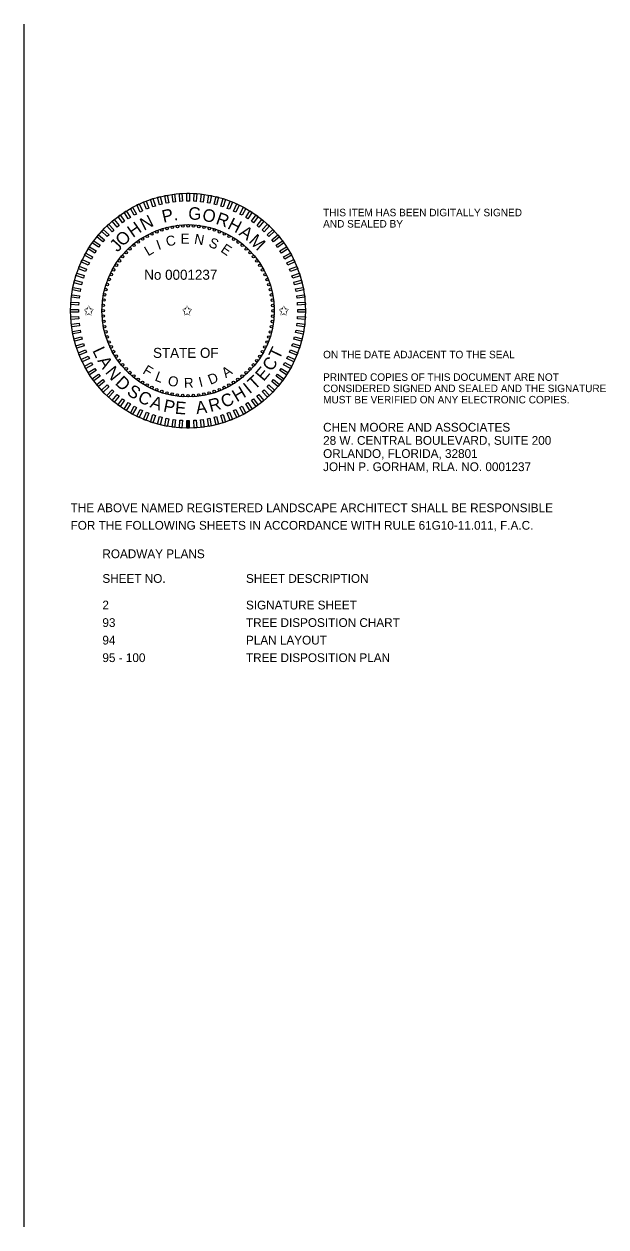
# Model space of a CAD drawing. Extents: x -811 to -790, y -2284 to -2178.
# Drawn here: x -803.09 to -798.44, y -2187.21 to -2177.61 of the extents above; entities that cross this region are included whole.
import ezdxf

# ---------------------------------------------------------------- set-up
doc = ezdxf.new("R2010")
doc.units = 0
for name, color, linetype in [('PlotBorder_dp', 7, 'Continuous'), ('TextMinor', 7, 'Continuous'), ('TextMisc', 7, 'Continuous'), ('TextNotes', 7, 'Continuous'), ('TextShtNo', 7, 'Continuous')]:
    doc.layers.add(name, color=color, linetype=linetype)

msp = doc.modelspace()

# ---------------------------------------------------------------- linework, layer by layer
at = {"layer": 'TextMinor'}
for radius in [0.9375, 0.6875]:
    msp.add_circle((-801.777, -2179.9009), radius, dxfattribs=at)
at = {"layer": 'TextNotes'}
msp.add_line((-803.0858, -2187.2129), (-803.0858, -2177.6129), dxfattribs=at)
at = {"layer": 'TextShtNo'}
for p, q in [((-801.787, -2180.8384), (-801.7871, -2180.7759)), ((-801.777, -2180.8384), (-801.7771, -2180.7759)), ((-801.767, -2180.8383), (-801.7671, -2180.7758))]:
    msp.add_line(p, q, dxfattribs=at)
for points in [[(-802.0377, -2179.0655), (-802.0569, -2179.0718), (-802.0762, -2179.0124), (-802.057, -2179.0061)], [(-801.9847, -2179.0508), (-802.0042, -2179.0558), (-802.0198, -2178.9953), (-802.0002, -2178.9903)], [(-801.9309, -2179.0394), (-801.9507, -2179.0432), (-801.9624, -2178.9819), (-801.9426, -2178.9781)], [(-801.8765, -2179.0315), (-801.8965, -2179.034), (-801.9044, -2178.972), (-801.8843, -2178.9695)], [(-801.8217, -2179.0269), (-801.8419, -2179.0282), (-801.8458, -2178.9659), (-801.8256, -2178.9646)], [(-801.7668, -2179.0258), (-801.787, -2179.0258), (-801.787, -2178.9634), (-801.7668, -2178.9634)], [(-801.7118, -2179.0282), (-801.732, -2179.0269), (-801.7281, -2178.9646), (-801.7079, -2178.9659)], [(-801.6572, -2179.034), (-801.6772, -2179.0315), (-801.6694, -2178.9695), (-801.6493, -2178.9721)], [(-801.603, -2179.0432), (-801.6228, -2179.0395), (-801.6111, -2178.9781), (-801.5913, -2178.9819)], [(-801.5495, -2179.0559), (-801.569, -2179.0508), (-801.5535, -2178.9904), (-801.5339, -2178.9954)], [(-801.4969, -2179.0718), (-801.5161, -2179.0656), (-801.4968, -2179.0062), (-801.4776, -2179.0124)], [(-802.2372, -2179.1566), (-802.2543, -2179.1674), (-802.2877, -2179.1147), (-802.2707, -2179.1039)], [(-802.1896, -2179.1292), (-802.2073, -2179.1389), (-802.2373, -2179.0842), (-802.2197, -2179.0745)], [(-802.1403, -2179.1048), (-802.1586, -2179.1134), (-802.1852, -2179.0569), (-802.1669, -2179.0483)], [(-802.0896, -2179.0835), (-802.1084, -2179.091), (-802.1314, -2179.0329), (-802.1126, -2179.0255)], [(-801.4454, -2179.091), (-801.4641, -2179.0836), (-801.4411, -2179.0256), (-801.4224, -2179.033)], [(-801.3952, -2179.1135), (-801.4134, -2179.1049), (-801.3868, -2179.0484), (-801.3686, -2179.057)], [(-801.3465, -2179.139), (-801.3642, -2179.1293), (-801.3341, -2179.0745), (-801.3164, -2179.0843)], [(-801.2995, -2179.1675), (-801.3165, -2179.1567), (-801.2831, -2179.104), (-801.266, -2179.1148)], [(-802.3269, -2179.2202), (-802.3424, -2179.233), (-802.3822, -2179.1849), (-802.3667, -2179.172)], [(-802.283, -2179.187), (-802.2994, -2179.1988), (-802.3361, -2179.1483), (-802.3197, -2179.1365)], [(-801.2544, -2179.1989), (-801.2707, -2179.1871), (-801.234, -2179.1366), (-801.2177, -2179.1484)], [(-801.2113, -2179.2331), (-801.2269, -2179.2203), (-801.1871, -2179.1722), (-801.1715, -2179.185)], [(-802.4447, -2179.3353), (-802.4575, -2179.3508), (-802.5057, -2179.311), (-802.4928, -2179.2955)], [(-802.4078, -2179.2944), (-802.4217, -2179.3092), (-802.4672, -2179.2664), (-802.4534, -2179.2517)], [(-802.3685, -2179.256), (-802.3832, -2179.2698), (-802.426, -2179.2243), (-802.4113, -2179.2105)], [(-801.1705, -2179.27), (-801.1852, -2179.2562), (-801.1425, -2179.2106), (-801.1278, -2179.2245)], [(-801.1321, -2179.3093), (-801.1459, -2179.2946), (-801.1004, -2179.2518), (-801.0866, -2179.2666)], [(-801.0962, -2179.351), (-801.1091, -2179.3354), (-801.061, -2179.2956), (-801.0481, -2179.3112)], [(-802.5103, -2179.4234), (-802.5211, -2179.4404), (-802.5738, -2179.407), (-802.563, -2179.3899)], [(-802.4789, -2179.3783), (-802.4907, -2179.3946), (-802.5413, -2179.3579), (-802.5294, -2179.3416)], [(-801.063, -2179.3948), (-801.0749, -2179.3784), (-801.0244, -2179.3417), (-801.0125, -2179.3581)], [(-801.0327, -2179.4406), (-801.0435, -2179.4236), (-800.9908, -2179.3901), (-800.98, -2179.4071)], [(-802.5388, -2179.4704), (-802.5486, -2179.4881), (-802.6033, -2179.458), (-802.5936, -2179.4403)], [(-801.0052, -2179.4882), (-801.015, -2179.4706), (-800.9603, -2179.4405), (-800.9505, -2179.4582)], [(-802.5868, -2179.5693), (-802.5942, -2179.588), (-802.6523, -2179.5651), (-802.6448, -2179.5463)], [(-802.5644, -2179.5191), (-802.573, -2179.5373), (-802.6295, -2179.5108), (-802.6209, -2179.4925)], [(-800.9809, -2179.5375), (-800.9895, -2179.5193), (-800.933, -2179.4927), (-800.9244, -2179.5109)], [(-800.9596, -2179.5882), (-800.967, -2179.5695), (-800.909, -2179.5465), (-800.9016, -2179.5652)], [(-802.622, -2179.6734), (-802.627, -2179.6929), (-802.6875, -2179.6774), (-802.6824, -2179.6579)], [(-802.606, -2179.6208), (-802.6122, -2179.64), (-802.6716, -2179.6207), (-802.6654, -2179.6015)], [(-800.9416, -2179.6402), (-800.9478, -2179.621), (-800.8885, -2179.6017), (-800.8822, -2179.6209)], [(-800.9269, -2179.6931), (-800.9319, -2179.6736), (-800.8714, -2179.658), (-800.8664, -2179.6776)], [(-802.6438, -2179.7811), (-802.6463, -2179.8011), (-802.7083, -2179.7933), (-802.7058, -2179.7733)], [(-802.6346, -2179.7269), (-802.6384, -2179.7467), (-802.6997, -2179.735), (-802.6959, -2179.7152)], [(-800.9155, -2179.7469), (-800.9193, -2179.7271), (-800.858, -2179.7154), (-800.8542, -2179.7352)], [(-800.9075, -2179.8013), (-800.9101, -2179.7813), (-800.8481, -2179.7735), (-800.8456, -2179.7935)], [(-802.6496, -2179.8358), (-802.6509, -2179.8559), (-802.7132, -2179.852), (-802.7119, -2179.8318)], [(-800.903, -2179.8561), (-800.9043, -2179.8359), (-800.842, -2179.832), (-800.8407, -2179.8522)], [(-802.652, -2179.8907), (-802.652, -2179.9109), (-802.7144, -2179.9109), (-802.7144, -2179.8907)], [(-802.6509, -2179.9456), (-802.6496, -2179.9658), (-802.7119, -2179.9697), (-802.7132, -2179.9496)], [(-800.9043, -2179.966), (-800.903, -2179.9458), (-800.8407, -2179.9498), (-800.842, -2179.9699)], [(-800.9019, -2179.9111), (-800.9019, -2179.8909), (-800.8395, -2179.8909), (-800.8395, -2179.9111)], [(-802.6464, -2180.0004), (-802.6438, -2180.0205), (-802.7058, -2180.0283), (-802.7083, -2180.0083)], [(-802.6384, -2180.0548), (-802.6346, -2180.0747), (-802.6959, -2180.0864), (-802.6997, -2180.0665)], [(-800.9193, -2180.0748), (-800.9155, -2180.055), (-800.8542, -2180.0667), (-800.858, -2180.0865)], [(-800.9101, -2180.0206), (-800.9076, -2180.0006), (-800.8456, -2180.0084), (-800.8481, -2180.0285)], [(-802.627, -2180.1086), (-802.622, -2180.1282), (-802.6825, -2180.1437), (-802.6875, -2180.1241)], [(-800.9319, -2180.1283), (-800.9269, -2180.1088), (-800.8664, -2180.1243), (-800.8715, -2180.1439)], [(-802.6123, -2180.1616), (-802.6061, -2180.1808), (-802.6654, -2180.2001), (-802.6717, -2180.1809)], [(-802.5943, -2180.2135), (-802.5869, -2180.2323), (-802.6449, -2180.2553), (-802.6523, -2180.2365)], [(-800.9671, -2180.2325), (-800.9597, -2180.2137), (-800.9016, -2180.2367), (-800.9091, -2180.2554)], [(-800.9479, -2180.181), (-800.9417, -2180.1618), (-800.8823, -2180.1811), (-800.8885, -2180.2003)], [(-802.573, -2180.2642), (-802.5644, -2180.2825), (-802.6209, -2180.3091), (-802.6295, -2180.2908)], [(-802.5487, -2180.3135), (-802.5389, -2180.3312), (-802.5936, -2180.3613), (-802.6034, -2180.3436)], [(-801.0151, -2180.3313), (-801.0053, -2180.3137), (-800.9506, -2180.3437), (-800.9603, -2180.3614)], [(-800.9895, -2180.2827), (-800.9809, -2180.2644), (-800.9244, -2180.291), (-800.933, -2180.3092)], [(-802.5212, -2180.3611), (-802.5104, -2180.3782), (-802.5631, -2180.4116), (-802.5739, -2180.3946)], [(-802.4909, -2180.407), (-802.479, -2180.4233), (-802.5295, -2180.46), (-802.5414, -2180.4437)], [(-801.075, -2180.4234), (-801.0632, -2180.4071), (-801.0126, -2180.4438), (-801.0245, -2180.4601)], [(-801.0436, -2180.3783), (-801.0328, -2180.3613), (-800.9801, -2180.3947), (-800.9909, -2180.4118)], [(-802.4577, -2180.4508), (-802.4448, -2180.4663), (-802.4929, -2180.5061), (-802.5058, -2180.4906)], [(-802.4218, -2180.4924), (-802.408, -2180.5072), (-802.4535, -2180.5499), (-802.4673, -2180.5352)], [(-802.3834, -2180.5318), (-802.3687, -2180.5456), (-802.4114, -2180.5911), (-802.4261, -2180.5773)], [(-801.1854, -2180.5457), (-801.1707, -2180.5319), (-801.1279, -2180.5774), (-801.1426, -2180.5912)], [(-801.1461, -2180.5073), (-801.1322, -2180.4926), (-801.0867, -2180.5353), (-801.1005, -2180.55)], [(-801.1092, -2180.4665), (-801.0964, -2180.4509), (-801.0482, -2180.4907), (-801.0611, -2180.5063)], [(-802.3426, -2180.5686), (-802.327, -2180.5815), (-802.3668, -2180.6296), (-802.3824, -2180.6167)], [(-802.2995, -2180.6028), (-802.2832, -2180.6147), (-802.3199, -2180.6652), (-802.3362, -2180.6533)], [(-802.2544, -2180.6342), (-802.2374, -2180.645), (-802.2708, -2180.6978), (-802.2879, -2180.6869)], [(-801.3167, -2180.6451), (-801.2996, -2180.6343), (-801.2662, -2180.687), (-801.2832, -2180.6979)], [(-801.2709, -2180.6148), (-801.2545, -2180.6029), (-801.2178, -2180.6534), (-801.2342, -2180.6653)], [(-801.227, -2180.5816), (-801.2115, -2180.5687), (-801.1717, -2180.6168), (-801.1872, -2180.6297)], [(-802.2074, -2180.6628), (-802.1897, -2180.6725), (-802.2198, -2180.7272), (-802.2375, -2180.7175)], [(-802.1587, -2180.6883), (-802.1405, -2180.6969), (-802.1671, -2180.7534), (-802.1853, -2180.7448)], [(-802.1085, -2180.7107), (-802.0898, -2180.7181), (-802.1128, -2180.7762), (-802.1315, -2180.7688)], [(-802.057, -2180.7299), (-802.0378, -2180.7362), (-802.0571, -2180.7955), (-802.0763, -2180.7893)], [(-801.5162, -2180.7362), (-801.497, -2180.73), (-801.4777, -2180.7894), (-801.4969, -2180.7956)], [(-801.4643, -2180.7182), (-801.4455, -2180.7108), (-801.4225, -2180.7688), (-801.4413, -2180.7763)], [(-801.4136, -2180.697), (-801.3953, -2180.6884), (-801.3687, -2180.7449), (-801.387, -2180.7535)], [(-801.3643, -2180.6726), (-801.3466, -2180.6628), (-801.3166, -2180.7176), (-801.3342, -2180.7273)], [(-802.0044, -2180.7459), (-801.9849, -2180.7509), (-802.0004, -2180.8114), (-802.02, -2180.8064)], [(-801.9509, -2180.7585), (-801.9311, -2180.7623), (-801.9428, -2180.8236), (-801.9626, -2180.8198)], [(-801.8967, -2180.7677), (-801.8767, -2180.7703), (-801.8845, -2180.8322), (-801.9046, -2180.8297)], [(-801.8421, -2180.7735), (-801.8219, -2180.7748), (-801.8258, -2180.8371), (-801.846, -2180.8358)], [(-801.7871, -2180.7759), (-801.767, -2180.7759), (-801.767, -2180.8383), (-801.7871, -2180.8383)], [(-801.7322, -2180.7748), (-801.712, -2180.7735), (-801.7081, -2180.8359), (-801.7283, -2180.8371)], [(-801.6774, -2180.7703), (-801.6574, -2180.7677), (-801.6495, -2180.8297), (-801.6696, -2180.8322)], [(-801.623, -2180.7623), (-801.6032, -2180.7585), (-801.5915, -2180.8199), (-801.6113, -2180.8236)], [(-801.5692, -2180.7509), (-801.5497, -2180.7459), (-801.5341, -2180.8064), (-801.5537, -2180.8114)]]:
    msp.add_lwpolyline(points, close=True, dxfattribs=at)
for centre in [(-802.0649, -2179.2876), (-802.0258, -2179.2708), (-801.9858, -2179.2564), (-801.9449, -2179.2445), (-801.9033, -2179.2353), (-801.8613, -2179.2287), (-801.8189, -2179.2247), (-801.7764, -2179.2234), (-801.7338, -2179.2248), (-801.6915, -2179.2288), (-801.6495, -2179.2355), (-801.6079, -2179.2448), (-801.5671, -2179.2567), (-801.527, -2179.2712), (-801.488, -2179.2881), (-802.2084, -2179.3785), (-802.1747, -2179.3525), (-802.1395, -2179.3286), (-802.1028, -2179.3069), (-801.4501, -2179.3075), (-801.4135, -2179.3292), (-801.3783, -2179.3531), (-801.3447, -2179.3792), (-802.2986, -2179.4686), (-802.2704, -2179.4367), (-802.2403, -2179.4066), (-801.3128, -2179.4074), (-801.2827, -2179.4375), (-801.2546, -2179.4695), (-802.3703, -2179.574), (-802.3487, -2179.5374), (-802.3247, -2179.5022), (-801.2285, -2179.5031), (-801.2046, -2179.5383), (-801.183, -2179.575), (-802.4066, -2179.651), (-802.3897, -2179.6119), (-801.1637, -2179.6129), (-801.1468, -2179.652), (-802.4423, -2179.7734), (-802.433, -2179.7318), (-802.4211, -2179.691), (-801.1325, -2179.6921), (-801.1206, -2179.7329), (-801.1114, -2179.7745), (-802.453, -2179.8578), (-802.449, -2179.8154), (-801.1048, -2179.8165), (-801.1008, -2179.8589), (-802.4544, -2179.9003), (-802.4531, -2179.9428), (-801.1009, -2179.944), (-801.0995, -2179.9014), (-802.4491, -2179.9852), (-802.4425, -2180.0273), (-802.4333, -2180.0688), (-801.1209, -2180.0699), (-801.1116, -2180.0284), (-801.1049, -2179.9863), (-802.4214, -2180.1097), (-802.4071, -2180.1497), (-801.1473, -2180.1508), (-801.1328, -2180.1108), (-802.3902, -2180.1888), (-802.3709, -2180.2267), (-802.3493, -2180.2634), (-801.2052, -2180.2644), (-801.1836, -2180.2277), (-801.1642, -2180.1898), (-802.3254, -2180.2986), (-802.2993, -2180.3323), (-801.2553, -2180.3331), (-801.2292, -2180.2995), (-802.2712, -2180.3642), (-802.2411, -2180.3943), (-802.2092, -2180.4225), (-802.1756, -2180.4486), (-801.3792, -2180.4493), (-801.3456, -2180.4232), (-801.3136, -2180.3951), (-801.2835, -2180.365), (-802.1404, -2180.4726), (-802.1038, -2180.4943), (-802.0659, -2180.5136), (-802.0269, -2180.5306), (-801.9868, -2180.545), (-801.5681, -2180.5454), (-801.5281, -2180.531), (-801.489, -2180.5141), (-801.4511, -2180.4948), (-801.4144, -2180.4732), (-801.946, -2180.5569), (-801.9044, -2180.5662), (-801.8624, -2180.5729), (-801.8201, -2180.577), (-801.777, -2180.5784), (-801.735, -2180.577), (-801.6926, -2180.5731), (-801.6506, -2180.5664), (-801.609, -2180.5572)]:
    msp.add_circle(centre, 0.01, dxfattribs=at)

# ---------------------------------------------------------------- texts
at = {"layer": 'PlotBorder_dp'}
for s, height, p in [('THIS ITEM HAS BEEN DIGITALLY SIGNED ', 0.06, (-800.6993, -2179.147)), ('AND SEALED BY', 0.06, (-800.6993, -2179.237)), ('ON THE DATE ADJACENT TO THE SEAL', 0.06, (-800.6993, -2180.2804)), ('PRINTED COPIES OF THIS DOCUMENT ARE NOT ', 0.06, (-800.6993, -2180.4604)), ('CONSIDERED SIGNED AND SEALED AND THE SIGNATURE ', 0.06, (-800.6993, -2180.5504)), ('MUST BE VERIFIED ON ANY ELECTRONIC COPIES.', 0.06, (-800.6993, -2180.6404)), ('CHEN MOORE AND ASSOCIATES', 0.07, (-800.6993, -2180.8657)), ('28 W. CENTRAL BOULEVARD, SUITE 200', 0.07, (-800.6993, -2180.9707)), ('ORLANDO, FLORIDA, 32801', 0.07, (-800.6993, -2181.0757)), ('JOHN P. GORHAM, RLA. NO. 0001237', 0.07, (-800.6993, -2181.1807)), ('THE ABOVE NAMED REGISTERED LANDSCAPE ARCHITECT SHALL BE RESPONSIBLE ', 0.07, (-802.7145, -2181.5084)), ('FOR THE FOLLOWING SHEETS IN ACCORDANCE WITH RULE 61G10-11.011, F.A.C.', 0.07, (-802.7145, -2181.6484)), ('ROADWAY PLANS', 0.07, (-802.4607, -2181.8755))]:
    msp.add_text(s, height=height, dxfattribs=at).set_placement(p)
at = {"layer": 'TextMisc'}
for s, p in [('SHEET NO.', (-802.4607, -2182.0725)), ('SHEET DESCRIPTION', (-801.3148, -2182.0725)), ('2', (-802.4607, -2182.2847)), ('SIGNATURE SHEET', (-801.3148, -2182.2847)), ('93', (-802.4607, -2182.4247)), ('TREE DISPOSITION CHART', (-801.3148, -2182.4247)), ('94', (-802.4607, -2182.5647)), ('PLAN LAYOUT', (-801.3148, -2182.5647)), ('95 - 100', (-802.4607, -2182.7047)), ('TREE DISPOSITION PLAN', (-801.3148, -2182.7047))]:
    msp.add_text(s, height=0.07, dxfattribs=at).set_placement(p)
at = {"layer": 'TextShtNo'}
for s, height, rotation, p in [('P', 0.1, 13.27214, (-801.9727, -2179.1996)), ('G', 0.1, 357.67775, (-801.7769, -2179.1728)), ('O', 0.1, 349.14372, (-801.6689, -2179.1808)), ('H', 0.1, 34.8941, (-802.2173, -2179.321)), ('N', 0.1, 26.60166, (-802.1291, -2179.2636)), ('.', 0.1, 6.53189, (-801.889, -2179.1814)), ('R', 0.1, 340.48286, (-801.5617, -2179.2053)), ('H', 0.1, 332.66151, (-801.469, -2179.2411)), ('O', 0.1, 43.55496, (-802.2996, -2179.394)), ('E', 0.08, 0.41861, (-801.8367, -2179.3658)), ('N', 0.08, 349.29143, (-801.7323, -2179.3643)), ('A', 0.1, 324.36906, (-801.3771, -2179.2924)), ('M', 0.1, 316.60207, (-801.2985, -2179.352)), ('J', 0.1, 48.19946, (-802.3389, -2179.4379)), ('L', 0.08, 30.40215, (-802.0961, -2179.4672)), ('I', 0.08, 20.01168, (-802.0126, -2179.4168)), ('C', 0.08, 12.20255, (-801.9447, -2179.3893)), ('S', 0.08, 337.02207, (-801.6193, -2179.3861)), ('E', 0.08, 325.86633, (-801.5227, -2179.4263)), ('L', 0.1, 295.24283, (-802.5424, -2180.2178)), ('T', 0.1, 64.19548, (-801.0493, -2180.2969)), ('A', 0.1, 301.50595, (-802.5032, -2180.2994)), ('N', 0.1, 309.27295, (-802.4427, -2180.3939)), ('F', 0.08, 328.72408, (-802.145, -2180.3975)), ('A', 0.08, 34.49917, (-801.4751, -2180.4403)), ('E', 0.1, 49.41645, (-801.1744, -2180.4694)), ('C', 0.1, 56.45868, (-801.1092, -2180.3912)), ('D', 0.1, 317.52311, (-802.3651, -2180.4843)), ('L', 0.08, 339.29159, (-802.0477, -2180.4565)), ('O', 0.08, 349.68206, (-801.943, -2180.4962)), ('R', 0.08, 2.33977, (-801.8085, -2180.5182)), ('I', 0.08, 14.20366, (-801.681, -2180.5115)), ('D', 0.08, 22.01279, (-801.5989, -2180.4928)), ('T', 0.1, 42.59164, (-801.2462, -2180.537)), ('S', 0.1, 326.00279, (-802.2726, -2180.5647)), ('H', 0.1, 30.766, (-801.3878, -2180.6322)), ('I', 0.1, 39.05844, (-801.2864, -2180.5685)), ('C', 0.1, 333.07522, (-802.1871, -2180.6207)), ('A', 0.1, 340.81202, (-802.0865, -2180.6693)), ('P', 0.1, 348.57901, (-801.9798, -2180.7041)), ('E', 0.1, 355.31927, (-801.8841, -2180.7224)), ('A', 0.1, 7.44085, (-801.7092, -2180.7266)), ('R', 0.1, 15.20785, (-801.5982, -2180.7098)), ('C', 0.1, 23.0292, (-801.4898, -2180.678))]:
    msp.add_text(s, height=height, rotation=rotation, dxfattribs=at).set_placement(p)
for s, p in [('No 0001237', (-802.1267, -2179.6536)), ('✩', (-802.6119, -2179.9388)), ('✩', (-801.8272, -2179.9388)), ('✩', (-801.0554, -2179.9388)), ('STATE OF', (-802.0567, -2180.2771))]:
    msp.add_text(s, height=0.08, dxfattribs=at).set_placement(p)

doc.saveas('drawing.dxf')
